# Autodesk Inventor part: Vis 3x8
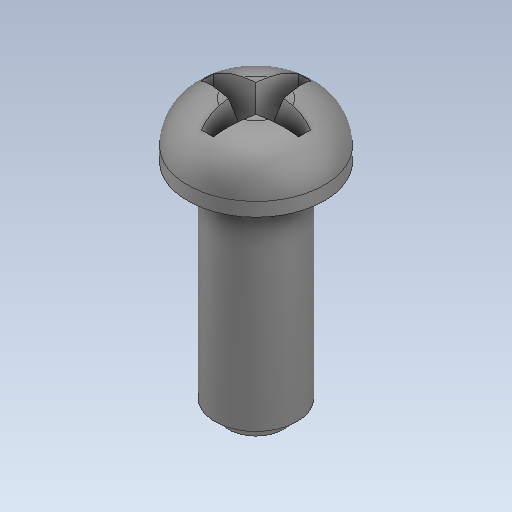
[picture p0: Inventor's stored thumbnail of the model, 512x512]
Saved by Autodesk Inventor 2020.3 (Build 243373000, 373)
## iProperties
Created: 2018-09
Part Number: Vis 3x8
Material: Générique
Document SubType Name: Modeling
Designer: ficho
Density: 1 g/cm^3
Appearance: Par défaut
Mass: 0.0843079 g
Surface Area: 1.44685 cm^2
Volume: 0.0843079 cm^3
Sending System: SolidWorks 2015
Last Author: adrien
Last Saved: 2019-01-14
Author: ficho
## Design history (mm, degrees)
feature "Enlèv. mat.-Extru.1"
node "Solide1"
